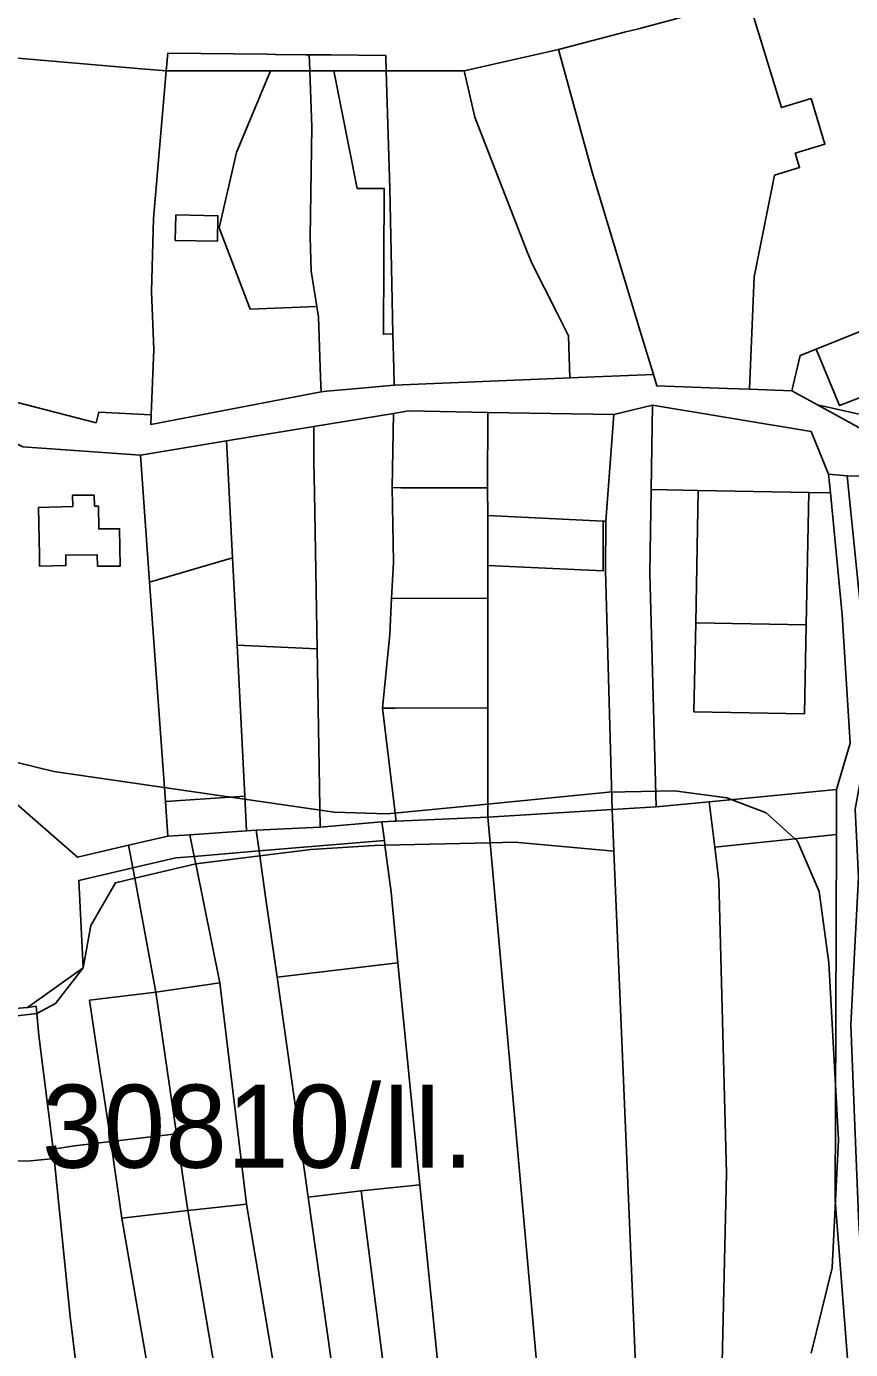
# Model space of a CAD drawing. Extents: x -535894 to -532827, y -1165802 to -1163635.
# Drawn here: x -534487.4 to -534338.4, y -1165184 to -1164945 of the extents above; entities that cross this region are included whole.
import ezdxf

# ---------------------------------------------------------------- set-up
doc = ezdxf.new("R2010")
doc.units = 0
for name, color, linetype in [('BPEJ_s', 7, 'Continuous'), ('orna_s', 7, 'Continuous'), ('ostatni_s', 7, 'Continuous'), ('sad_s', 7, 'Continuous'), ('zahrada_s', 7, 'Continuous')]:
    doc.layers.add(name, color=color, linetype=linetype)

msp = doc.modelspace()

# ---------------------------------------------------------------- linework, layer by layer
at = {"layer": 'BPEJ_s'}
for points in [[(-534517.62, -1165071), (-534482.42, -1165079.6), (-534457.09, -1165083.27), (-534431.76, -1165086.94), (-534422.13, -1165087.25), (-534406.52, -1165085.73), (-534382.16, -1165083.358), (-534370.2, -1165083.11), (-534360.73, -1165084.38), (-534353.64, -1165087.09), (-534347.997, -1165092.167), (-534344.08, -1165101.26), (-534342.33, -1165114.17), (-534340.58, -1165146.18), (-534341.69, -1165169.28), (-534345.52, -1165184.73)], [(-534345.52, -1165184.73), (-534341.69, -1165169.28), (-534340.58, -1165146.18), (-534342.33, -1165114.17), (-534344.08, -1165101.26), (-534347.997, -1165092.167), (-534353.64, -1165087.09), (-534360.73, -1165084.38), (-534370.2, -1165083.11), (-534382.16, -1165083.358), (-534406.52, -1165085.73), (-534422.13, -1165087.25), (-534431.76, -1165086.94), (-534457.09, -1165083.27), (-534482.42, -1165079.6), (-534517.62, -1165071)]]:
    msp.add_lwpolyline(points, dxfattribs=at)
at = {"layer": 'orna_s'}
for points in [[(-534363.95, -1165085.07), (-534340.91, -1165082.87), (-534340.93, -1165090.96), (-534362.94, -1165093.25)], [(-534373.53, -1165086), (-534363.95, -1165085.07), (-534362.94, -1165093.25), (-534362.19, -1165099.37), (-534360.8, -1165152.21), (-534363.2, -1165257.26), (-534368.13, -1165254.92), (-534376.79, -1165251.88), (-534375.61, -1165225.35), (-534381.19, -1165093.99), (-534381.51, -1165086.49)], [(-534403.97, -1165087.87), (-534403.56, -1165092.47), (-534422.55, -1165092.92), (-534422.66, -1165092.09), (-534423.1, -1165088.71), (-534420.94, -1165088.56), (-534420.53, -1165088.55)], [(-534403.97, -1165087.87), (-534381.51, -1165086.49), (-534381.19, -1165093.99), (-534399.08, -1165092.35), (-534403.56, -1165092.47)], [(-534422.55, -1165092.92), (-534403.56, -1165092.47), (-534391.54, -1165226.66), (-534389.65, -1165251.4), (-534397.29, -1165252.4), (-534405.45, -1165253.73), (-534408.79, -1165228.57), (-534416.26, -1165154.3), (-534420.23, -1165114.18), (-534421.45, -1165101.43)], [(-534403.56, -1165092.47), (-534399.08, -1165092.35), (-534381.19, -1165093.99), (-534375.61, -1165225.35), (-534391.54, -1165226.66)], [(-534362.94, -1165093.25), (-534340.93, -1165090.96), (-534341.17, -1165157.05), (-534338.8, -1165187.24), (-534348.24, -1165186.88), (-534348.28, -1165269.23), (-534358.8, -1165260.74), (-534363.2, -1165257.26), (-534360.8, -1165152.21), (-534362.19, -1165099.37)], [(-534445.18, -1165094.85), (-534456.75, -1165096.28), (-534457.02, -1165094.93), (-534445.3, -1165093.96)], [(-534456.75, -1165096.28), (-534445.18, -1165094.85), (-534444.13, -1165102.22), (-534442.07, -1165116.76), (-534436.45, -1165156.54), (-534425.58, -1165233.37), (-534425.2, -1165235.77), (-534435.5, -1165237.88), (-534440.98, -1165197.04), (-534447.57, -1165157.79), (-534452.39, -1165117.81)], [(-534458.2, -1165158.95), (-534447.57, -1165157.79), (-534440.98, -1165197.04), (-534435.5, -1165237.88), (-534444.47, -1165239.8)]]:
    msp.add_lwpolyline(points, close=True, dxfattribs=at)
at = {"layer": 'ostatni_s'}
for points in [[(-534356.81, -1164940.14), (-534350.88, -1164959.65), (-534345.52, -1164958.02), (-534343.02, -1164966.25), (-534348.38, -1164967.88), (-534347.59, -1164970.48), (-534352.12, -1164971.86), (-534355.84, -1164990.24), (-534356.63, -1165010.51), (-534360.64, -1165010.37), (-534373.42, -1165009.91), (-534374.04, -1165007.87), (-534376.24, -1165000.61), (-534385.1, -1164971.33), (-534391.17, -1164949.12), (-534389.78, -1164948.76), (-534379.25, -1164946.03), (-534376.73, -1164945.38), (-534369.96, -1164943.59)], [(-534391.17, -1164949.12), (-534385.1, -1164971.33), (-534376.24, -1165000.61), (-534374.04, -1165007.87), (-534389.11, -1165008.45), (-534389.4, -1165000.85), (-534391.5, -1164996.69), (-534395.95, -1164987.86), (-534396.87, -1164985.71), (-534400.13, -1164977.32), (-534406.33, -1164961.38), (-534408.23, -1164953)], [(-534466.57, -1164952.61), (-534462.09, -1164953), (-534464.37, -1164979.65), (-534464.75, -1164992.87), (-534464.33, -1165003.32), (-534464.79, -1165015.17), (-534474.29, -1165014.68), (-534474.77, -1165016.57), (-534494.86, -1165011.42), (-534497.44, -1165010.75), (-534499.22, -1165009.6), (-534494.31, -1165002.21), (-534492.53, -1164986.26), (-534492.33, -1164984.55), (-534491.63, -1164978.28), (-534489.63, -1164950.63)], [(-534461.81, -1164949.81), (-534443.96, -1164950), (-534442.32, -1164950.03), (-534436.91, -1164950.08), (-534436.26, -1164950.09), (-534436.21, -1164951.47), (-534436.16, -1164953), (-534443.26, -1164953), (-534445.31, -1164953), (-534462.09, -1164953)], [(-534436.26, -1164950.09), (-534432.36, -1164950.13), (-534422.4, -1164950.24), (-534422.33, -1164953), (-534431.79, -1164953.01), (-534436.16, -1164953), (-534436.21, -1164951.47)], [(-534462.09, -1164953), (-534445.31, -1164953), (-534443.26, -1164953), (-534449.41, -1164967.75), (-534452.51, -1164981.34), (-534446.93, -1164996.06), (-534434.88, -1164995.57), (-534434.58, -1164997.44), (-534434.2, -1165008.42), (-534434.11, -1165010.99), (-534464.85, -1165016.92), (-534464.79, -1165015.17), (-534464.33, -1165003.32), (-534464.75, -1164992.87), (-534464.37, -1164979.65)], [(-534443.26, -1164953), (-534436.16, -1164953), (-534435.79, -1164963.16), (-534436.1, -1164982.98), (-534435.88, -1164989.17), (-534434.88, -1164995.57), (-534446.93, -1164996.06), (-534452.51, -1164981.34), (-534449.41, -1164967.75)], [(-534436.16, -1164953), (-534431.79, -1164953.01), (-534427.58, -1164974.26), (-534422.68, -1164974.25), (-534422.82, -1165000.59), (-534421.11, -1165000.5), (-534420.98, -1165006.79), (-534420.92, -1165009.8), (-534427.49, -1165010.4), (-534433.05, -1165010.9), (-534434.11, -1165010.99), (-534434.2, -1165008.42), (-534434.58, -1164997.44), (-534434.88, -1164995.57), (-534435.88, -1164989.17), (-534436.1, -1164982.98), (-534435.79, -1164963.16)], [(-534422.33, -1164953), (-534408.23, -1164953), (-534406.33, -1164961.38), (-534400.13, -1164977.32), (-534396.87, -1164985.71), (-534395.95, -1164987.86), (-534391.5, -1164996.69), (-534389.4, -1165000.85), (-534389.11, -1165008.45), (-534390.4, -1165008.5), (-534420.92, -1165009.8), (-534420.98, -1165006.79), (-534421.11, -1165000.5), (-534421.31, -1164991.48), (-534421.68, -1164974.24)], [(-534460.38, -1164979.04), (-534460.47, -1164983.64), (-534452.83, -1164983.78), (-534452.78, -1164979.17)], [(-534460.38, -1164979.04), (-534452.78, -1164979.17), (-534452.83, -1164983.78), (-534460.47, -1164983.64)], [(-534326.13, -1164999.26), (-534323.17, -1165006.94), (-534326.34, -1165008.07), (-534340.41, -1165013.49), (-534344.59, -1165003.27), (-534335.33, -1164999.55), (-534334.18, -1165002.41), (-534329.35, -1165000.46), (-534328.08, -1164999.98)], [(-534374.22, -1165013.39), (-534345.52, -1165018.15), (-534342.35, -1165025.88), (-534342.03, -1165029.27), (-534345.92, -1165029.2), (-534365.92, -1165028.8), (-534374.46, -1165028.64)], [(-534403.97, -1165014.71), (-534403.99, -1165028.33), (-534407.71, -1165028.33), (-534419.68, -1165028.32), (-534421.26, -1165028.31), (-534420.99, -1165014.89), (-534418.3, -1165014.45)], [(-534435.41, -1165017.27), (-534435.39, -1165023.63), (-534435.28, -1165029.23), (-534434.81, -1165057.43), (-534449.3, -1165056.79), (-534450.11, -1165041.01), (-534450.96, -1165024.44), (-534451.2, -1165019.87)], [(-534451.2, -1165019.87), (-534450.96, -1165024.44), (-534450.11, -1165041.01), (-534465.11, -1165045.38), (-534466.76, -1165022.45)], [(-534342.35, -1165025.88), (-534339, -1165026.19), (-534336.45, -1165051.12), (-534335.3, -1165074.14), (-534337.54, -1165086.43), (-534336.94, -1165098.71), (-534337.66, -1165112.41), (-534338.34, -1165125.36), (-534337.61, -1165143.65), (-534336.91, -1165161.4), (-534335.9, -1165174.28), (-534335.39, -1165187.36), (-534338.8, -1165187.24), (-534341.17, -1165157.05), (-534340.93, -1165090.96), (-534340.91, -1165082.87), (-534338.44, -1165074.49), (-534339.89, -1165051.28), (-534342.03, -1165029.27)], [(-534479.02, -1165029.69), (-534475.11, -1165029.69), (-534475.04, -1165031.63), (-534474.35, -1165031.67), (-534474.28, -1165035.76), (-534470.53, -1165035.74), (-534470.45, -1165042.5), (-534474.52, -1165042.52), (-534474.56, -1165040.45), (-534480.25, -1165040.49), (-534480.24, -1165042.39), (-534485.01, -1165042.48), (-534485.01, -1165040.52), (-534485.18, -1165031.88), (-534478.99, -1165031.69)], [(-534419.68, -1165028.32), (-534407.71, -1165028.33), (-534403.99, -1165028.33), (-534403.98, -1165033.35), (-534403.98, -1165042.36), (-534403.98, -1165048.34), (-534421.36, -1165048.3), (-534421.04, -1165041.75), (-534421.26, -1165028.31)], [(-534345.92, -1165029.2), (-534346.39, -1165053.08), (-534366.38, -1165052.71), (-534365.92, -1165028.8)], [(-534403.98, -1165033.35), (-534383.14, -1165034.35), (-534383.14, -1165043.35), (-534403.98, -1165042.36)], [(-534447.89, -1165084.07), (-534447.57, -1165090.34), (-534457.81, -1165091.02), (-534461.79, -1165091.28), (-534462.24, -1165085.02)], [(-534447.57, -1165090.34), (-534445.83, -1165090.22), (-534445.3, -1165093.96), (-534457.02, -1165094.93), (-534457.81, -1165091.02)], [(-534434.26, -1165089.65), (-534423.1, -1165088.71), (-534422.66, -1165092.09), (-534445.3, -1165093.96), (-534445.83, -1165090.22)], [(-534461.79, -1165091.28), (-534457.81, -1165091.02), (-534457.02, -1165094.93), (-534460.35, -1165095.21), (-534468.13, -1165097.01), (-534468.89, -1165092.92)], [(-534467.78, -1165098.88), (-534471.25, -1165099.69), (-534475.74, -1165107.41), (-534477.12, -1165115.1), (-534477.91, -1165099.28), (-534468.13, -1165097.01)], [(-534471.25, -1165099.69), (-534467.78, -1165098.88), (-534463.97, -1165119.47), (-534475.96, -1165120.89), (-534475.24, -1165125.77), (-534474.04, -1165133.88), (-534473.77, -1165135.32), (-534472.14, -1165146.47), (-534478.68, -1165147.25), (-534482.54, -1165147.81), (-534485.11, -1165127.29), (-534485.47, -1165123.31), (-534482.11, -1165121.5), (-534477.12, -1165115.1), (-534475.74, -1165107.41)], [(-534442.07, -1165116.76), (-534420.23, -1165114.18), (-534416.26, -1165154.3), (-534426.83, -1165155.34), (-534436.45, -1165156.54)], [(-534482.11, -1165121.5), (-534485.47, -1165123.31), (-534485.59, -1165122.03), (-534487.16, -1165122.22), (-534477.12, -1165115.1)], [(-534463.97, -1165119.47), (-534452.39, -1165117.81), (-534447.57, -1165157.79), (-534458.2, -1165158.95), (-534460.23, -1165145.05)], [(-534463.97, -1165119.47), (-534460.23, -1165145.05), (-534472.14, -1165146.47), (-534473.77, -1165135.32), (-534474.04, -1165133.88), (-534475.24, -1165125.77), (-534475.96, -1165120.89)], [(-534485.59, -1165122.03), (-534485.47, -1165123.31), (-534508.47, -1165126.04), (-534508.71, -1165123.9), (-534487.16, -1165122.22)], [(-534508.47, -1165126.04), (-534485.47, -1165123.31), (-534485.11, -1165127.29), (-534482.54, -1165147.81), (-534482.37, -1165149.5), (-534486.55, -1165149.95), (-534505.88, -1165150.21), (-534506.66, -1165142.89), (-534507.16, -1165138.28), (-534508.07, -1165129.82)]]:
    msp.add_lwpolyline(points, close=True, dxfattribs=at)
for points in [[(-534369.96, -1164943.59), (-534376.73, -1164945.38), (-534379.25, -1164946.03), (-534389.78, -1164948.76), (-534391.17, -1164949.12), (-534408.23, -1164953), (-534422.33, -1164953), (-534422.4, -1164950.24), (-534432.36, -1164950.13), (-534436.26, -1164950.09), (-534436.91, -1164950.08), (-534442.32, -1164950.03), (-534443.96, -1164950), (-534461.81, -1164949.81), (-534462.09, -1164953), (-534466.57, -1164952.61), (-534489.63, -1164950.63)], [(-534494.86, -1165011.42), (-534474.77, -1165016.57), (-534474.29, -1165014.68), (-534464.79, -1165015.17), (-534464.85, -1165016.92), (-534434.11, -1165010.99), (-534433.05, -1165010.9), (-534427.49, -1165010.4), (-534420.92, -1165009.8), (-534390.4, -1165008.5), (-534389.11, -1165008.45), (-534374.04, -1165007.87), (-534373.42, -1165009.91), (-534360.64, -1165010.37), (-534356.63, -1165010.51), (-534348.99, -1165010.79), (-534344.37, -1165013.33), (-534327.77, -1165022.47)], [(-534336.09, -1165026.21), (-534339, -1165026.19), (-534342.35, -1165025.88), (-534345.52, -1165018.15), (-534374.22, -1165013.39), (-534381.21, -1165015.12), (-534403.97, -1165014.71), (-534418.3, -1165014.45), (-534420.99, -1165014.89), (-534435.41, -1165017.27), (-534451.2, -1165019.87), (-534466.76, -1165022.45), (-534488.01, -1165020.91)], [(-534491.48, -1165083.48), (-534478.11, -1165095.05), (-534468.89, -1165092.92), (-534468.13, -1165097.01), (-534477.91, -1165099.28), (-534477.12, -1165115.1), (-534487.16, -1165122.22), (-534508.71, -1165123.9)]]:
    msp.add_lwpolyline(points, dxfattribs=at)
at = {"layer": 'sad_s'}
msp.add_lwpolyline([(-534526.42, -1165144.06), (-534506.66, -1165142.89), (-534505.88, -1165150.21), (-534486.55, -1165149.95), (-534482.37, -1165149.5), (-534479.49, -1165178.1), (-534474.69, -1165217.27), (-534470.72, -1165237.94), (-534490.64, -1165243.85), (-534498.4, -1165244.45), (-534504.24, -1165246.32), (-534515.07, -1165249.99), (-534525.69, -1165253.61), (-534525.52, -1165245.33), (-534526.56, -1165167.24), (-534526.49, -1165154.6)], close=True, dxfattribs=at)
at = {"layer": 'zahrada_s'}
for points in [[(-534371.08, -1164939.34), (-534357.43, -1164937.18), (-534334.97, -1164941.39), (-534333.48, -1164948.48), (-534333.57, -1164963.39), (-534333.62, -1164973.53), (-534334.15, -1164983.38), (-534333.78, -1164990.52), (-534333.36, -1164998.76), (-534335.33, -1164999.55), (-534344.59, -1165003.27), (-534347.52, -1165004.44), (-534348.99, -1165010.79), (-534356.63, -1165010.51), (-534355.84, -1164990.24), (-534352.12, -1164971.86), (-534347.59, -1164970.48), (-534348.38, -1164967.88), (-534343.02, -1164966.25), (-534345.52, -1164958.02), (-534350.88, -1164959.65), (-534356.81, -1164940.14), (-534369.96, -1164943.59)], [(-534431.79, -1164953.01), (-534422.33, -1164953), (-534421.68, -1164974.24), (-534421.31, -1164991.48), (-534421.11, -1165000.5), (-534422.82, -1165000.59), (-534422.68, -1164974.25), (-534427.58, -1164974.26)], [(-534344.59, -1165003.27), (-534340.41, -1165013.49), (-534326.34, -1165008.07), (-534323.17, -1165006.94), (-534316.46, -1165011.48), (-534307.96, -1165011.06), (-534307.68, -1165013.89), (-534311.71, -1165018.18), (-534316.13, -1165017.8), (-534323.68, -1165017.15), (-534329.82, -1165016.63), (-534344.37, -1165013.33), (-534348.99, -1165010.79), (-534347.52, -1165004.44)], [(-534381.21, -1165015.12), (-534374.22, -1165013.39), (-534374.46, -1165028.64), (-534374.69, -1165043.74), (-534373.53, -1165086), (-534381.51, -1165086.49), (-534382.68, -1165043.37), (-534382.64, -1165034.37)], [(-534344.37, -1165013.33), (-534329.82, -1165016.63), (-534323.68, -1165017.15), (-534316.13, -1165017.8), (-534311.71, -1165018.18), (-534313.73, -1165020.34), (-534327.77, -1165022.47)], [(-534488.01, -1165020.91), (-534466.76, -1165022.45), (-534465.11, -1165045.38), (-534462.24, -1165085.02), (-534461.79, -1165091.28), (-534468.89, -1165092.92), (-534478.11, -1165095.05), (-534491.48, -1165083.48), (-534497.01, -1165041.71), (-534499.24, -1165024.85), (-534500.56, -1165014.81)], [(-534420.99, -1165014.89), (-534421.26, -1165028.31), (-534421.04, -1165041.75), (-534421.36, -1165048.3), (-534421.67, -1165054.78), (-534423.03, -1165068.16), (-534420.53, -1165088.55), (-534420.94, -1165088.56), (-534423.1, -1165088.71), (-534434.26, -1165089.65), (-534434.81, -1165057.43), (-534435.28, -1165029.23), (-534435.39, -1165023.63), (-534435.41, -1165017.27)], [(-534381.21, -1165015.12), (-534382.64, -1165034.37), (-534383.14, -1165034.35), (-534403.98, -1165033.35), (-534403.99, -1165028.33), (-534403.97, -1165014.71)], [(-534339, -1165026.19), (-534336.09, -1165026.21), (-534336.35, -1165040.51), (-534336.45, -1165051.12)], [(-534479.02, -1165029.69), (-534478.99, -1165031.69), (-534485.18, -1165031.88), (-534485.01, -1165040.52), (-534485.01, -1165042.48), (-534480.24, -1165042.39), (-534480.25, -1165040.49), (-534474.56, -1165040.45), (-534474.52, -1165042.52), (-534470.45, -1165042.5), (-534470.53, -1165035.74), (-534474.28, -1165035.76), (-534474.35, -1165031.67), (-534475.04, -1165031.63), (-534475.11, -1165029.69)], [(-534365.92, -1165028.8), (-534366.38, -1165052.71), (-534366.7, -1165068.79), (-534346.71, -1165069.18), (-534346.39, -1165053.08), (-534345.92, -1165029.2), (-534342.03, -1165029.27), (-534339.89, -1165051.28), (-534338.44, -1165074.49), (-534340.91, -1165082.87), (-534363.95, -1165085.07), (-534373.53, -1165086), (-534374.69, -1165043.74), (-534374.46, -1165028.64)], [(-534383.14, -1165034.35), (-534382.64, -1165034.37), (-534382.68, -1165043.37), (-534381.51, -1165086.49), (-534403.97, -1165087.87), (-534403.97, -1165068.1), (-534403.98, -1165048.34), (-534403.98, -1165042.36), (-534383.14, -1165043.35)], [(-534450.11, -1165041.01), (-534449.3, -1165056.79), (-534447.89, -1165084.07), (-534462.24, -1165085.02), (-534465.11, -1165045.38)], [(-534403.98, -1165048.34), (-534403.97, -1165068.1), (-534420.73, -1165068.15), (-534423.03, -1165068.16), (-534421.67, -1165054.78), (-534421.36, -1165048.3)], [(-534366.38, -1165052.71), (-534346.39, -1165053.08), (-534346.71, -1165069.18), (-534366.7, -1165068.79)], [(-534434.81, -1165057.43), (-534434.26, -1165089.65), (-534445.83, -1165090.22), (-534447.57, -1165090.34), (-534447.89, -1165084.07), (-534449.3, -1165056.79)], [(-534420.73, -1165068.15), (-534403.97, -1165068.1), (-534403.97, -1165087.87), (-534420.53, -1165088.55), (-534423.03, -1165068.16)], [(-534422.55, -1165092.92), (-534424.46, -1165092.97), (-534435.96, -1165093.7), (-534445.18, -1165094.85), (-534445.3, -1165093.96), (-534422.66, -1165092.09)], [(-534460.35, -1165095.21), (-534457.02, -1165094.93), (-534456.75, -1165096.28), (-534467.78, -1165098.88), (-534468.13, -1165097.01)], [(-534424.46, -1165092.97), (-534422.55, -1165092.92), (-534421.45, -1165101.43), (-534420.23, -1165114.18), (-534442.07, -1165116.76), (-534444.13, -1165102.22), (-534445.18, -1165094.85), (-534435.96, -1165093.7)], [(-534467.78, -1165098.88), (-534456.75, -1165096.28), (-534452.39, -1165117.81), (-534463.97, -1165119.47)], [(-534472.14, -1165146.47), (-534460.23, -1165145.05), (-534458.2, -1165158.95), (-534470.12, -1165160.31)], [(-534478.68, -1165147.25), (-534472.14, -1165146.47), (-534470.12, -1165160.31), (-534455.8, -1165243.06), (-534461.02, -1165244.38), (-534470.72, -1165237.94), (-534474.69, -1165217.27), (-534479.49, -1165178.1), (-534482.37, -1165149.5), (-534482.54, -1165147.81)], [(-534426.83, -1165155.34), (-534416.26, -1165154.3), (-534408.79, -1165228.57), (-534417.1, -1165232.13)], [(-534436.45, -1165156.54), (-534426.83, -1165155.34), (-534417.1, -1165232.13), (-534408.79, -1165228.57), (-534405.45, -1165253.73), (-534415.33, -1165254.24), (-534421.35, -1165253.74), (-534423.92, -1165242.4), (-534425.2, -1165235.77), (-534425.58, -1165233.37)], [(-534470.12, -1165160.31), (-534458.2, -1165158.95), (-534444.47, -1165239.8), (-534455.8, -1165243.06)]]:
    msp.add_lwpolyline(points, close=True, dxfattribs=at)

# ---------------------------------------------------------------- texts
at = {"layer": 'BPEJ_s'}
msp.add_text('30810/II.', height=15, dxfattribs=at).set_placement((-534484.594, -1165151.192))

doc.saveas('drawing.dxf')
